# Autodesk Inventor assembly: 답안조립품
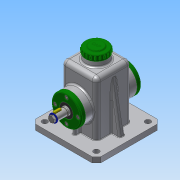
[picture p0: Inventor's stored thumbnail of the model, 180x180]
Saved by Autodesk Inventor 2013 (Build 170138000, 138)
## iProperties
Created: 2018-10
Part Number: 답안조립품
Document SubType Name: Assembly
Designer: Administrator
Author: Administrator
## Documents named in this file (14)
- C:\Users\Administrator\Desktop\481013V1003\답안조립품.iam
- C:\Users\Administrator\Desktop\481013V1003\1.본체.ipt
- C:\Users\Administrator\Desktop\481013V1003\V-벨트풀리.ipt
- C:\Users\Administrator\Desktop\481013V1003\뒤커버.ipt
- C:\Users\Administrator\Desktop\481013V1003\멈춤링 15 x 1.ipt
- C:\Users\Administrator\Desktop\481013V1003\베어링 15 x 35 x 11.ipt
- C:\Users\Administrator\Desktop\481013V1003\볼트 M4 x 10.ipt
- C:\Users\Administrator\Desktop\481013V1003\볼트 M6 x 12.ipt
- C:\Users\Administrator\Desktop\481013V1003\상부캡.ipt
- C:\Users\Administrator\Desktop\481013V1003\앞커버.ipt
- C:\Users\Administrator\Desktop\481013V1003\오일실 15 25 7.ipt
- C:\Users\Administrator\Desktop\481013V1003\와셔.ipt
- C:\Users\Administrator\Desktop\481013V1003\축.ipt
- C:\Users\Administrator\Desktop\481013V1003\키 5 x 5 x 14.ipt
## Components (2 placed, 2 different names)
1. 1.본체:1
2. V-벨트풀리:1 — 플러쉬:1
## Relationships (1: Flush 1)
- 플러쉬:1 [Flush]: V-벨트풀리:1
